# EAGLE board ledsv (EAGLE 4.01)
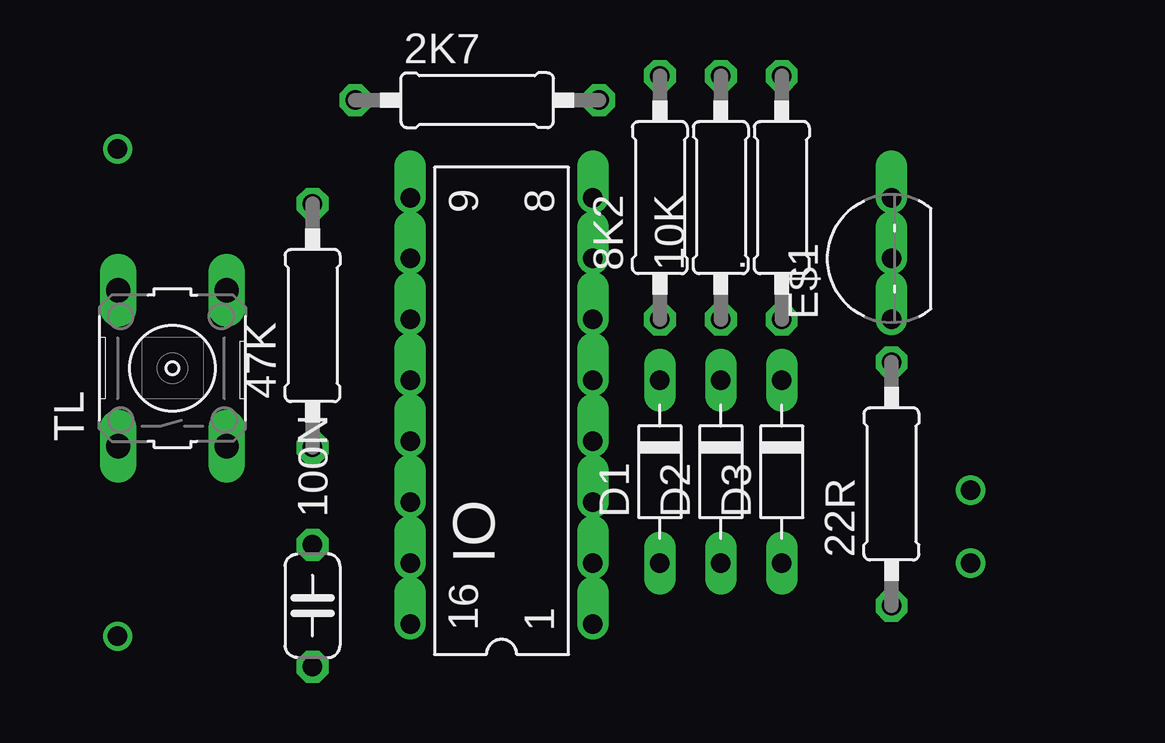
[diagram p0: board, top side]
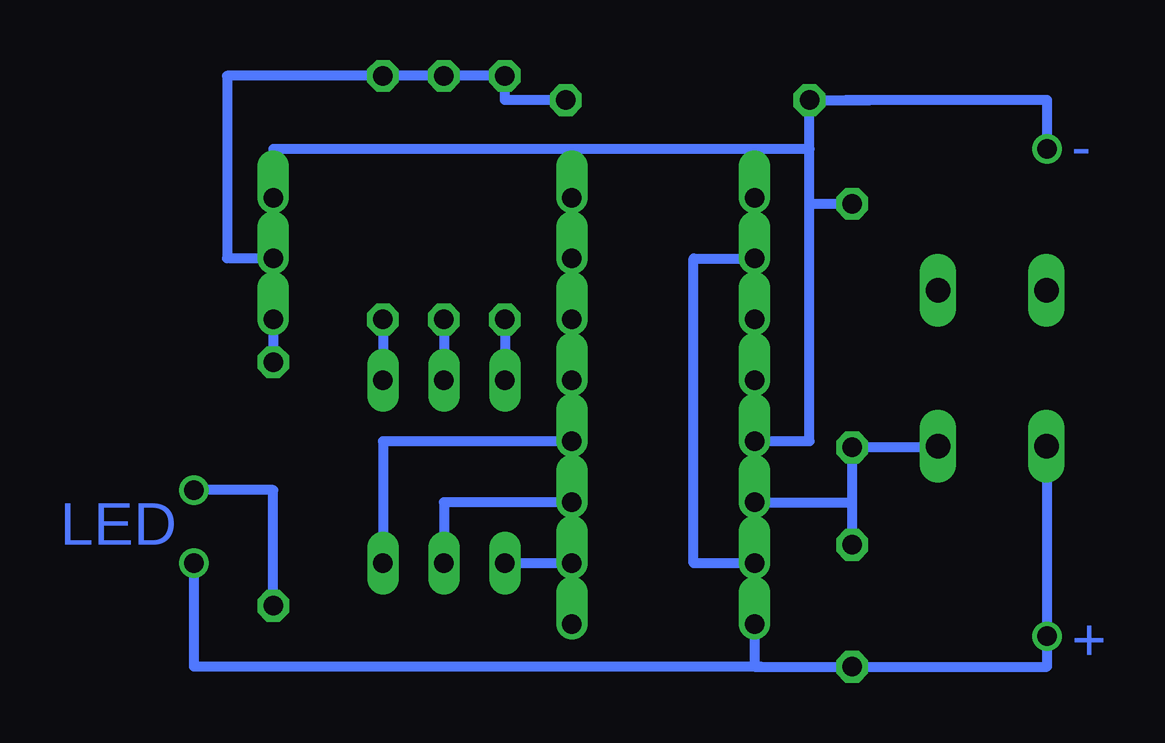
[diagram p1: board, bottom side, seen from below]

No outline drawn. Coordinates in mm, seen from the top.
Copper layers used: Bottom

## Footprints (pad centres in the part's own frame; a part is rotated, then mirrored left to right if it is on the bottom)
0207/10 = drill 0.813 octagon: 1 -5.08,0; 2 5.08,0
C050-024X044 = drill 0.813 octagon: 1 -2.54,0; 2 2.54,0
D-7.5 = drill 0.813 long: A -3.81,0; K 3.81,0
TO92- = drill 0.813 offset: 1 2.54,-1.27; 2 0,-1.27; 3 -2.54,-1.27
DIL16 = drill 0.813 offset: 1 -8.89,-3.81; 2 -6.35,-3.81; 3 -3.81,-3.81; 4 -1.27,-3.81; 5 1.27,-3.81; 6 3.81,-3.81; 7 6.35,-3.81; 8 8.89,-3.81; 9 8.89,3.81; 10 6.35,3.81; 11 3.81,3.81; 12 1.27,3.81; 13 -1.27,3.81; 14 -3.81,3.81; 15 -6.35,3.81; 16 -8.89,3.81
B3F-10XX = drill 1.016 long: 1 -3.251,2.261; 2 3.251,2.261; 3 -3.251,-2.261; 4 3.251,-2.261

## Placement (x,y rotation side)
2K7  [0207/10]  -11.18,78.99 0 top
8K2  [0207/10]  -3.56,74.93 90 top
10K  [0207/10]  -1.02,74.93 90 top
22R  [0207/10]  6.1,62.99 90 top
47K  [0207/10]  -18.03,69.6 90 top
100N  [C050-024X044]  -18.03,57.91 90 top
.  3k3  [0207/10]  1.52,74.93 90 top
D1  [D-7.5]  -3.56,63.5 90 top
D2  [D-7.5]  -1.02,63.5 90 top
D3  [D-7.5]  1.52,63.5 90 top
E$1  [TO92-]  4.83,72.39 90 top
IO  [DIL16]  -10.16,66.04 90 top
TL  [B3F-10XX]  -23.88,67.82 90 top

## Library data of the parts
2K7 8K2 10K 22R 47K 100N . = rcl
D1-D3 = diode
E$1 = transistor-npn
IO = 40xx
TL = switch-omron

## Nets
S$1: IO.10 IO.15
S$2: E$1.2
S$3: 47K.1 100N.2
S$4: 100N.1 IO.16
S$5: D1.A IO.2
S$6: D2.A IO.3
S$7: D3.A IO.4
S$8: 8K2.1 D1.K
S$9: 10K.1 D2.K
S$10: ..1 D3.K
S$11: 2K7.2 8K2.2 ..2
S$12: 22R.2
S$13: 22R.1
S$14: 2K7.1 47K.2 IO.8

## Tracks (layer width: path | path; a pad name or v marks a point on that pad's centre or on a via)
S$1
  Bottom 0.406: IO.15 -11.43,59.69 -11.43,72.39 IO.10
S$2
  Bottom 0.406: E$1.2 7.87,72.39
S$3
  Bottom 0.406: -13.97,62.23 -18.03,62.23 | -18.03,62.23 100N.2 | -18.03,62.23 47K.1 -21.59,64.52
S$4  (via drill 0.81)
  Bottom 0.406: IO.16 -13.97,55.37 -14.22,55.37 | -14.22,55.37 100N.1 -26.16,55.37 v-26.16,56.64 -26.16,64.52 | -14.22,55.37 9.4,55.37 v9.4,59.69
S$5
  Bottom 0.406: IO.2 D1.A
S$6
  Bottom 0.406: IO.3 -1.02,62.23 D2.A
S$7
  Bottom 0.406: IO.4 1.52,64.77 D3.A
S$8
  Bottom 0.406: 8K2.1 D1.K
S$9
  Bottom 0.406: 10K.1 D2.K
S$10
  Bottom 0.406: ..1 D3.K
S$11
  Bottom 0.406: 2K7.2 -3.56,78.99 8K2.2 ..2 8.03,80.01 8.03,72.39
S$12
  Bottom 0.406: 6.1,69.6 22R.2
S$13  (via drill 0.81)
  Bottom 0.406: 22R.1 6.1,62.74 v9.4,62.74
S$14  (via drill 0.81)
  Bottom 0.406: -24.13,78.99 -26.16,78.99 v-26.16,76.96 | -24.13,78.99 -23.88,78.99 | 6.1,74.93 6.1,76.96 -6.35,76.96 | -6.35,76.96 IO.8 | -16.26,76.96 2K7.1 -17.78,78.99 | -16.26,76.96 -6.35,76.96 | -16.26,74.68 -16.26,76.96 | -16.26,74.68 47K.2 | -14.22,64.77 -16.26,64.77 -16.26,74.68 | -17.78,78.99 -18.8,78.99 | -24.13,78.99 -17.78,78.99

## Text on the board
Bottom: - | LED | +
